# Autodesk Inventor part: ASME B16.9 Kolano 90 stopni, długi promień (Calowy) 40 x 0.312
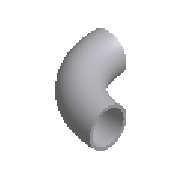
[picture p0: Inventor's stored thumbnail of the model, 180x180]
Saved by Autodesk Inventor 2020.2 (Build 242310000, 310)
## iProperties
Manager: www.cadconsulting.pl
Company: Fabian Stasiak CAD Consulting
Created: 2014-02
Part Number: ASME B16.9 Kolano 90 stopni, długi promień (Calowy) 40 x 0.312
Material: Stal kuta
Description: Element kuty, spawany doczołowo - Kolano 90º o długim promieniu - calowe
Document SubType Name: Modeling
Standard: ASME B16.9
Designer: F.Stasiak
Standard Revision: 2003
Standards Organization: ANSI
Language: pl-PL
Size Designation: 40 x 0.312
Categories: <MemberInstance><Categories><Category DisplayName="Rury cienko- i grubościenne" InternalName="4347fa0f-2144-441d-94cd-e3e15c92b736" Mnemonic="TUBEANDPIPE"><Cate
Density: 1 g/cm^3
Appearance: Stal
Catalog Web Link: www.expertbooks.pl
IsCustomPart: 0
NAME: PIPING: ASME B16.9 Long Radius 90 Deg Elbow
DATA: <meta><inlinegroups number="0" deflen="0"></inlinegroups><connections number="2"></connections><angles><a>1.57079632679489</a></angles></meta>
Author: F.Stasiak
Subject: Zbiór ćwiczeń. Autodesk Inventor 2020. Kurs Professional
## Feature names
1. Sweep1
## Parameters: d0 = 1000.1504 mm, d1 = 1016 mm, OD = 1016 mm, A = 1524 mm, d2 = 1524 mm, d3 = 1524 mm, d4 = 0, T = 7.9248 mm, d5 = 0, Size_Designation = 12.345 mm
